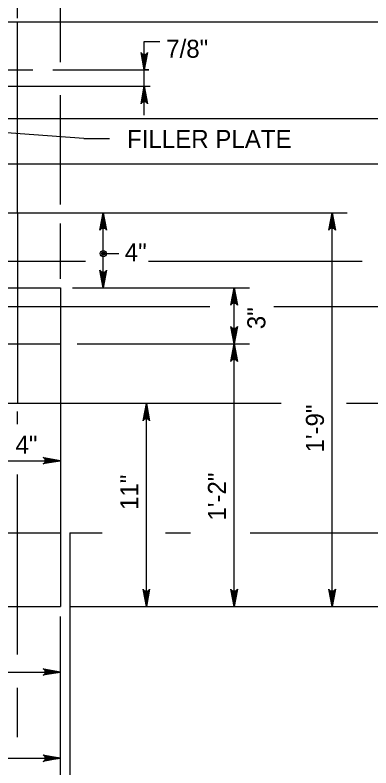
# Model space of a CAD drawing. Extents: x 632007860 to 635435983, y 295418622 to 297794622.
# Drawn here: x 633962266 to 634022495, y 296727373 to 296854867 of the extents above; entities that cross this region are included whole.
import ezdxf

# ---------------------------------------------------------------- set-up
doc = ezdxf.new("R2010")
doc.units = 0
for name, color, linetype in [('8', 7, 'Continuous'), ('S-ABUT', 7, 'Continuous'), ('S-DETL-DIMS', 7, 'Continuous'), ('S-DETL-T120', 7, 'Continuous'), ('S-GRND-MAJR', 7, 'Continuous'), ('S-MISC-CNTR-WT01', 7, 'Continuous'), ('S-STEL', 7, 'Continuous')]:
    doc.layers.add(name, color=color, linetype=linetype)

msp = doc.modelspace()

# ---------------------------------------------------------------- linework, layer by layer
at = {"layer": '8'}
for p, q in [((633950022, 296845585), (633965296, 296845585)), ((633868306, 296821376), (634018483, 296821376))]:
    msp.add_line(p, q, dxfattribs=at)
at = {"layer": 'S-ABUT'}
for p, q in [((633865978, 296808674), (633969961, 296808674)), ((633969961, 296808674), (633969961, 296789628)), ((633912811, 296799164), (633969961, 296799164)), ((633969961, 296789628), (633969961, 296754701)), ((633971555, 296767196), (633976994, 296767196)), ((633971555, 296767196), (633971555, 296754701)), ((633987716, 296767196), (633991975, 296767196)), ((634002066, 296767196), (634072742, 296767196)), ((633971555, 296754701), (634072704, 296754701))]:
    msp.add_line(p, q, dxfattribs=at)
at = {"layer": 'S-DETL-DIMS'}
for p, q in [((633969961, 296846899), (633969961, 296869036)), ((633962703, 296854323), (633962703, 296858534)), ((633984136, 296850367), (633986749, 296850367)), ((633984136, 296837916), (633984136, 296850367)), ((633968673, 296845585), (633984923, 296845585)), ((633959201, 296842808), (633985151, 296842808)), ((633969961, 296834842), (633969961, 296841289)), ((633973915, 296833972), (633945604, 296836022)), ((633969961, 296822786), (633969961, 296834842)), ((633973915, 296833972), (633978247, 296833972)), ((633974399, 296821376), (633979236, 296821376)), ((633977192, 296808689), (633977192, 296821376)), ((634012871, 296821376), (634018483, 296821376)), ((634015921, 296754701), (634015921, 296821376)), ((633969961, 296810224), (633969961, 296819544)), ((633977192, 296814478), (633979805, 296814478)), ((633971968, 296808674), (634001961, 296808674)), ((633999339, 296754701), (633999339, 296808674)), ((633972790, 296799164), (634001961, 296799164)), ((633984492, 296754701), (633984492, 296789099)), ((633962703, 296785580), (633962703, 296787717)), ((633957262, 296779400), (633969961, 296779400)), ((633962703, 296746592), (633962703, 296777080)), ((633972456, 296754701), (634028836, 296754701)), ((633969961, 296690900), (633969961, 296752996)), ((633912811, 296743613), (633969961, 296743613)), ((633962703, 296732601), (633962703, 296740966)), ((633897731, 296729014), (633969961, 296729014))]:
    msp.add_line(p, q, dxfattribs=at)
for points in [[(633984136, 296845585), (633983581, 296848544), (633983660, 296848430), (633983739, 296848316), (633983838, 296848258), (633983938, 296848199), (633984037, 296848182), (633984136, 296848165), (633984235, 296848182), (633984334, 296848199), (633984434, 296848258), (633984533, 296848316), (633984612, 296848430), (633984691, 296848544), (633984136, 296845585), (633984612, 296848430), (633984533, 296848316), (633984136, 296845585), (633984434, 296848258), (633984334, 296848199), (633984136, 296845585), (633984235, 296848182), (633984136, 296848165), (633984136, 296845585), (633984037, 296848182), (633983938, 296848199), (633984136, 296845585), (633983838, 296848258), (633983739, 296848316), (633984136, 296845585), (633983660, 296848430)], [(633984136, 296842808), (633984691, 296839848), (633984612, 296839962), (633984533, 296840076), (633984434, 296840135), (633984334, 296840194), (633984235, 296840211), (633984136, 296840228), (633984037, 296840211), (633983938, 296840194), (633983838, 296840135), (633983739, 296840076), (633983660, 296839962), (633983581, 296839848), (633984136, 296842808), (633983660, 296839962), (633983739, 296840076), (633984136, 296842808), (633983838, 296840135), (633983938, 296840194), (633984136, 296842808), (633984037, 296840211), (633984136, 296840228), (633984136, 296842808), (633984235, 296840211), (633984334, 296840194), (633984136, 296842808), (633984434, 296840135), (633984533, 296840076), (633984136, 296842808), (633984612, 296839962)], [(633977192, 296821376), (633977747, 296818417), (633977668, 296818531), (633977589, 296818645), (633977490, 296818704), (633977391, 296818763), (633977291, 296818780), (633977192, 296818797), (633977093, 296818780), (633976994, 296818763), (633976894, 296818704), (633976795, 296818645), (633976716, 296818531), (633976637, 296818417), (633977192, 296821376), (633976716, 296818531), (633976795, 296818645), (633977192, 296821376), (633976894, 296818704), (633976994, 296818763), (633977192, 296821376), (633977093, 296818780), (633977192, 296818797), (633977192, 296821376), (633977291, 296818780), (633977391, 296818763), (633977192, 296821376), (633977490, 296818704), (633977589, 296818645), (633977192, 296821376), (633977668, 296818531)], [(634015921, 296821376), (634016476, 296818417), (634016397, 296818531), (634016318, 296818645), (634016218, 296818704), (634016119, 296818763), (634016020, 296818780), (634015921, 296818797), (634015821, 296818780), (634015722, 296818763), (634015623, 296818704), (634015524, 296818645), (634015445, 296818531), (634015366, 296818417), (634015921, 296821376), (634015445, 296818531), (634015524, 296818645), (634015921, 296821376), (634015623, 296818704), (634015722, 296818763), (634015921, 296821376), (634015821, 296818780), (634015921, 296818797), (634015921, 296821376), (634016020, 296818780), (634016119, 296818763), (634015921, 296821376), (634016218, 296818704), (634016318, 296818645), (634015921, 296821376), (634016397, 296818531)], [(633977192, 296808689), (633976637, 296811648), (633976716, 296811534), (633976795, 296811420), (633976894, 296811361), (633976994, 296811303), (633977093, 296811286), (633977192, 296811269), (633977291, 296811286), (633977391, 296811303), (633977490, 296811361), (633977589, 296811420), (633977668, 296811534), (633977747, 296811648), (633977192, 296808689), (633977668, 296811534), (633977589, 296811420), (633977192, 296808689), (633977490, 296811361), (633977391, 296811303), (633977192, 296808689), (633977291, 296811286), (633977192, 296811269), (633977192, 296808689), (633977093, 296811286), (633976994, 296811303), (633977192, 296808689), (633976894, 296811361), (633976795, 296811420), (633977192, 296808689), (633976716, 296811534)], [(633999339, 296808674), (633999894, 296805714), (633999815, 296805828), (633999736, 296805942), (633999637, 296806001), (633999537, 296806060), (633999438, 296806077), (633999339, 296806094), (633999240, 296806077), (633999141, 296806060), (633999041, 296806001), (633998942, 296805942), (633998863, 296805828), (633998784, 296805714), (633999339, 296808674), (633998863, 296805828), (633998942, 296805942), (633999339, 296808674), (633999041, 296806001), (633999141, 296806060), (633999339, 296808674), (633999240, 296806077), (633999339, 296806094), (633999339, 296808674), (633999438, 296806077), (633999537, 296806060), (633999339, 296808674), (633999637, 296806001), (633999736, 296805942), (633999339, 296808674), (633999815, 296805828)], [(633999339, 296799164), (633998784, 296802123), (633998863, 296802009), (633998942, 296801895), (633999041, 296801836), (633999141, 296801778), (633999240, 296801761), (633999339, 296801744), (633999438, 296801761), (633999537, 296801778), (633999637, 296801836), (633999736, 296801895), (633999815, 296802009), (633999894, 296802123), (633999339, 296799164), (633999815, 296802009), (633999736, 296801895), (633999339, 296799164), (633999637, 296801836), (633999537, 296801778), (633999339, 296799164), (633999438, 296801761), (633999339, 296801744), (633999339, 296799164), (633999240, 296801761), (633999141, 296801778), (633999339, 296799164), (633999041, 296801836), (633998942, 296801895), (633999339, 296799164), (633998863, 296802009)], [(633999339, 296799164), (633999894, 296796205), (633999815, 296796319), (633999736, 296796433), (633999637, 296796491), (633999537, 296796550), (633999438, 296796567), (633999339, 296796584), (633999240, 296796567), (633999141, 296796550), (633999041, 296796491), (633998942, 296796433), (633998863, 296796319), (633998784, 296796205), (633999339, 296799164), (633998863, 296796319), (633998942, 296796433), (633999339, 296799164), (633999041, 296796491), (633999141, 296796550), (633999339, 296799164), (633999240, 296796567), (633999339, 296796584), (633999339, 296799164), (633999438, 296796567), (633999537, 296796550), (633999339, 296799164), (633999637, 296796491), (633999736, 296796433), (633999339, 296799164), (633999815, 296796319)], [(633984492, 296789099), (633985046, 296786140), (633984967, 296786254), (633984888, 296786368), (633984789, 296786427), (633984690, 296786485), (633984591, 296786502), (633984492, 296786519), (633984392, 296786502), (633984293, 296786485), (633984194, 296786427), (633984095, 296786368), (633984016, 296786254), (633983937, 296786140), (633984492, 296789099), (633984016, 296786254), (633984095, 296786368), (633984492, 296789099), (633984194, 296786427), (633984293, 296786485), (633984492, 296789099), (633984392, 296786502), (633984492, 296786519), (633984492, 296789099), (633984591, 296786502), (633984690, 296786485), (633984492, 296789099), (633984789, 296786427), (633984888, 296786368), (633984492, 296789099), (633984967, 296786254)], [(633969961, 296779400), (633967002, 296778845), (633967116, 296778924), (633967230, 296779003), (633967288, 296779102), (633967347, 296779201), (633967364, 296779300), (633967381, 296779400), (633967364, 296779499), (633967347, 296779598), (633967288, 296779697), (633967230, 296779797), (633967116, 296779876), (633967002, 296779955), (633969961, 296779400), (633967116, 296779876), (633967230, 296779797), (633969961, 296779400), (633967288, 296779697), (633967347, 296779598), (633969961, 296779400), (633967364, 296779499), (633967381, 296779400), (633969961, 296779400), (633967364, 296779300), (633967347, 296779201), (633969961, 296779400), (633967288, 296779102), (633967230, 296779003), (633969961, 296779400), (633967116, 296778924)], [(633984492, 296754701), (633983937, 296757661), (633984016, 296757546), (633984095, 296757432), (633984194, 296757374), (633984293, 296757315), (633984392, 296757298), (633984492, 296757281), (633984591, 296757298), (633984690, 296757315), (633984789, 296757374), (633984888, 296757432), (633984967, 296757546), (633985046, 296757661), (633984492, 296754701), (633984967, 296757546), (633984888, 296757432), (633984492, 296754701), (633984789, 296757374), (633984690, 296757315), (633984492, 296754701), (633984591, 296757298), (633984492, 296757281), (633984492, 296754701), (633984392, 296757298), (633984293, 296757315), (633984492, 296754701), (633984194, 296757374), (633984095, 296757432), (633984492, 296754701), (633984016, 296757546)], [(633999339, 296754701), (633998784, 296757661), (633998863, 296757546), (633998942, 296757432), (633999041, 296757374), (633999141, 296757315), (633999240, 296757298), (633999339, 296757281), (633999438, 296757298), (633999537, 296757315), (633999637, 296757374), (633999736, 296757432), (633999815, 296757546), (633999894, 296757661), (633999339, 296754701), (633999815, 296757546), (633999736, 296757432), (633999339, 296754701), (633999637, 296757374), (633999537, 296757315), (633999339, 296754701), (633999438, 296757298), (633999339, 296757281), (633999339, 296754701), (633999240, 296757298), (633999141, 296757315), (633999339, 296754701), (633999041, 296757374), (633998942, 296757432), (633999339, 296754701), (633998863, 296757546)], [(634015921, 296754701), (634015366, 296757661), (634015445, 296757546), (634015524, 296757432), (634015623, 296757374), (634015722, 296757315), (634015821, 296757298), (634015921, 296757281), (634016020, 296757298), (634016119, 296757315), (634016218, 296757374), (634016318, 296757432), (634016397, 296757546), (634016476, 296757661), (634015921, 296754701), (634016397, 296757546), (634016318, 296757432), (634015921, 296754701), (634016218, 296757374), (634016119, 296757315), (634015921, 296754701), (634016020, 296757298), (634015921, 296757281), (634015921, 296754701), (634015821, 296757298), (634015722, 296757315), (634015921, 296754701), (634015623, 296757374), (634015524, 296757432), (634015921, 296754701), (634015445, 296757546)], [(633969961, 296743613), (633967002, 296743058), (633967116, 296743137), (633967230, 296743216), (633967288, 296743315), (633967347, 296743414), (633967364, 296743514), (633967381, 296743613), (633967364, 296743712), (633967347, 296743811), (633967288, 296743911), (633967230, 296744010), (633967116, 296744089), (633967002, 296744168), (633969961, 296743613), (633967116, 296744089), (633967230, 296744010), (633969961, 296743613), (633967288, 296743911), (633967347, 296743811), (633969961, 296743613), (633967364, 296743712), (633967381, 296743613), (633969961, 296743613), (633967364, 296743514), (633967347, 296743414), (633969961, 296743613), (633967288, 296743315), (633967230, 296743216), (633969961, 296743613), (633967116, 296743137)], [(633969961, 296729014), (633967002, 296728459), (633967116, 296728538), (633967230, 296728617), (633967288, 296728716), (633967347, 296728816), (633967364, 296728915), (633967381, 296729014), (633967364, 296729113), (633967347, 296729212), (633967288, 296729312), (633967230, 296729411), (633967116, 296729490), (633967002, 296729569), (633969961, 296729014), (633967116, 296729490), (633967230, 296729411), (633969961, 296729014), (633967288, 296729312), (633967347, 296729212), (633969961, 296729014), (633967364, 296729113), (633967381, 296729014), (633969961, 296729014), (633967364, 296728915), (633967347, 296728816), (633969961, 296729014), (633967288, 296728716), (633967230, 296728617), (633969961, 296729014), (633967116, 296728538)]]:
    msp.add_lwpolyline(points, dxfattribs=at)
for radius in [529, 265]:
    msp.add_circle((633977192, 296814478), radius, dxfattribs=at)
at = {"layer": 'S-GRND-MAJR'}
for p, q in [((633912811, 296767196), (633969961, 296767196)), ((633801783, 296754701), (633969961, 296754701))]:
    msp.add_line(p, q, dxfattribs=at)
at = {"layer": 'S-MISC-CNTR-WT01'}
msp.add_line((633984923, 296845585), (633984178, 296845585), dxfattribs=at)
at = {"layer": 'S-STEL'}
for p, q in [((633973817, 296853655), (633867808, 296853655)), ((633962703, 296821377), (633962703, 296853655)), ((634072742, 296853655), (633973817, 296853655)), ((634072742, 296837318), (633895173, 296837318)), ((634033434, 296829622), (633939667, 296829622)), ((633962703, 296821377), (633962703, 296789099)), ((633974193, 296813131), (633896444, 296813131)), ((634021018, 296813131), (633984858, 296813131)), ((633995233, 296805436), (633940134, 296805436)), ((634072742, 296805436), (634006060, 296805436)), ((634007300, 296789099), (633867808, 296789099)), ((634072704, 296789099), (634018337, 296789099)), ((633971555, 296754701), (633971555, 296721897))]:
    msp.add_line(p, q, dxfattribs=at)

# ---------------------------------------------------------------- texts
at = {"layer": 'S-DETL-T120'}
for s, height, p in [('7/8"', 3048, (633987841, 296847637)), ('FILLER PLATE', 3048.01, (633981211, 296832365)), ('4"', 3048, (633980830, 296813184)), ('4"', 3048, (633962338, 296780573))]:
    msp.add_text(s, height=height, dxfattribs=at).set_placement(p)
for s, p in [('3"', (634004625, 296801671)), ('1\'-9"', (634014539, 296780794)), ('11"', (633983110, 296771054)), ('1\'-2"', (633997958, 296769268))]:
    msp.add_text(s, height=3048, rotation=90, dxfattribs=at).set_placement(p)

doc.saveas('drawing.dxf')
